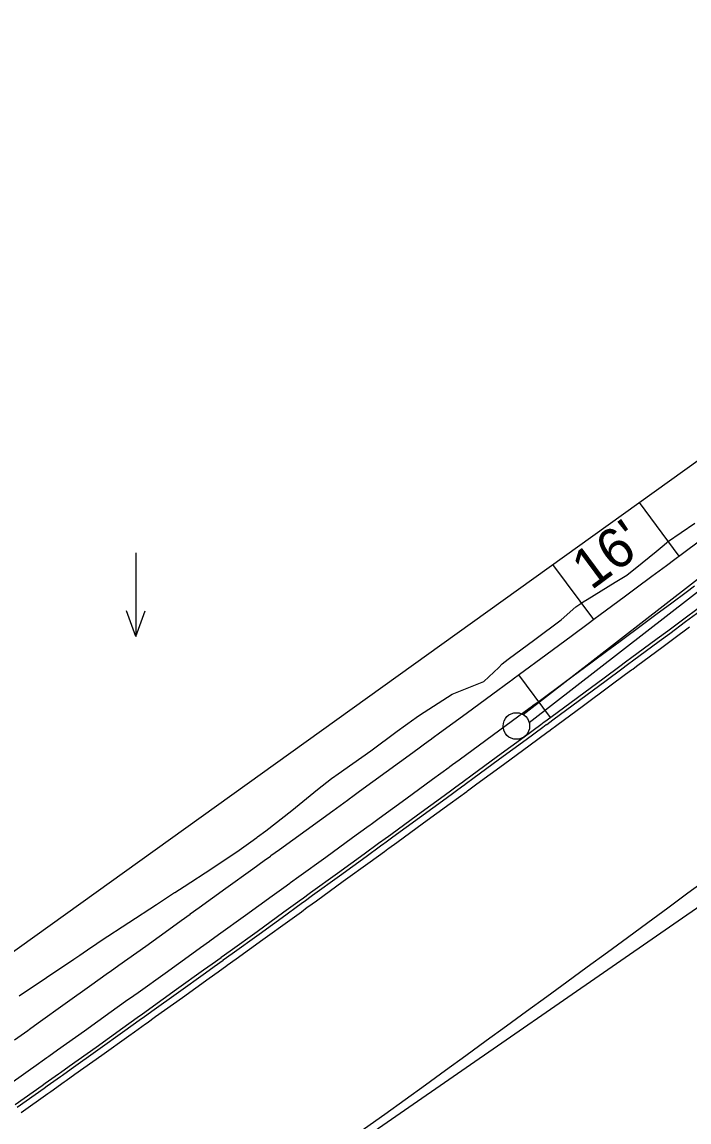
# Model space of a CAD drawing. Extents: x 1147550 to 1149124, y 2017436 to 2018779.
# Drawn here: x 1148333.9 to 1148434.3, y 2018092.6 to 2018257.9 of the extents above; entities that cross this region are included whole.
import ezdxf

# ---------------------------------------------------------------- set-up
doc = ezdxf.new("R2010")
doc.units = 0
for name, color, linetype in [('S_EDGE_CONCRETE', 7, 'Continuous'), ('S_HEADWALL', 7, 'Continuous'), ('S_MAILBOX', 7, 'Continuous'), ('S_SECONDARY_CTL', 7, 'Continuous'), ('S_TANK', 7, 'Continuous'), ('S_TELEPHONE_UTILITIES', 7, 'Continuous'), ('S_TELEPHONE_UTILITIES_ANNOT', 7, 'Continuous')]:
    doc.layers.add(name, color=color, linetype=linetype)

msp = doc.modelspace()

# ---------------------------------------------------------------- linework, layer by layer
at = {"layer": 'S_EDGE_CONCRETE'}
msp.add_line((1148293.22, 2018026.54), (1148491.47, 2018163.46), dxfattribs=at)
msp.add_arc((1145037.29, 2022741.09), 5729.58, 304.629463, 309.445337, dxfattribs=at)
at = {"layer": 'S_HEADWALL'}
for p, q in [((1148426.77, 2018185.69), (1148432.74, 2018177.64)), ((1148413.76, 2018176.37), (1148419.89, 2018168.11)), ((1148408.63, 2018159.79), (1148413.39, 2018153.37))]:
    msp.add_line(p, q, dxfattribs=at)
at = {"layer": 'S_MAILBOX'}
msp.add_lwpolyline([(1147550.1, 2017525.89), (1147894.72, 2017801.4), (1147903.55, 2017831.14), (1148035.64, 2017933.4), (1148261.5, 2018084.85), (1148285.74, 2018084.65), (1148479.1, 2018223.18), (1148835.76, 2018573.62)], dxfattribs=at)
at = {"layer": 'S_SECONDARY_CTL'}
msp.add_lwpolyline([(1148333.49, 2018111.55), (1148337.61, 2018114.33), (1148341.74, 2018117.07), (1148342.64, 2018117.69), (1148344.28, 2018118.81), (1148344.53, 2018118.98), (1148345.83, 2018119.87), (1148349.99, 2018122.59), (1148354.15, 2018125.3), (1148355.51, 2018126.18), (1148356.88, 2018127.08), (1148356.92, 2018127.1), (1148358.31, 2018128.01), (1148362.5, 2018130.68), (1148366.63, 2018133.43), (1148368.37, 2018134.7), (1148369.27, 2018135.36), (1148369.37, 2018135.43), (1148370.62, 2018136.38), (1148374.55, 2018139.42), (1148378.37, 2018142.59), (1148380.5, 2018144.22), (1148380.99, 2018144.57), (1148381.14, 2018144.67), (1148382.37, 2018145.53), (1148386.43, 2018148.38), (1148390.4, 2018151.36), (1148392.9, 2018153.14), (1148393.01, 2018153.22), (1148393.46, 2018153.52), (1148394.46, 2018154.21), (1148398.65, 2018156.88), (1148403.39, 2018158.81), (1148405.66, 2018160.92), (1148406.13, 2018161.39), (1148406.19, 2018161.44), (1148407.08, 2018162.16), (1148411.08, 2018165.1), (1148415.04, 2018168.08), (1148417.27, 2018170), (1148418.16, 2018170.63), (1148418.37, 2018170.77), (1148418.95, 2018171.15), (1148423.19, 2018173.75), (1148424.92, 2018174.76), (1148427.25, 2018176.62), (1148429.33, 2018178.36), (1148430.53, 2018179.36), (1148430.94, 2018179.7), (1148431.06, 2018179.8), (1148435.18, 2018182.58)], dxfattribs=at)
at = {"layer": 'S_TANK'}
for p, q in [((1148351.07, 2018178.15), (1148351.07, 2018165.58)), ((1148351.07, 2018165.58), (1148349.67, 2018169.43)), ((1148351.07, 2018165.58), (1148352.47, 2018169.43))]:
    msp.add_line(p, q, dxfattribs=at)
at = {"layer": 'S_TELEPHONE_UTILITIES'}
for points in [[(1148332.79, 2018104.94), (1148334.79, 2018106.36), (1148335.08, 2018106.57), (1148336.38, 2018107.5), (1148340.42, 2018110.38), (1148344.46, 2018113.26), (1148345.35, 2018113.89), (1148346.97, 2018115.06), (1148347.22, 2018115.23), (1148348.5, 2018116.15), (1148352.54, 2018119.04), (1148356.57, 2018121.94), (1148357.88, 2018122.88), (1148359.21, 2018123.84), (1148359.25, 2018123.86), (1148360.6, 2018124.83), (1148364.62, 2018127.74), (1148368.65, 2018130.64), (1148370.39, 2018131.9), (1148371.3, 2018132.56), (1148371.39, 2018132.63), (1148372.67, 2018133.55), (1148376.69, 2018136.46), (1148380.71, 2018139.38), (1148382.88, 2018140.95), (1148383.36, 2018141.31), (1148383.51, 2018141.41), (1148384.72, 2018142.3), (1148388.73, 2018145.22), (1148392.74, 2018148.15), (1148395.23, 2018149.96), (1148395.34, 2018150.04), (1148395.77, 2018150.36), (1148396.75, 2018151.08), (1148400.75, 2018154.01), (1148404.76, 2018156.95), (1148407.24, 2018158.77), (1148407.77, 2018159.16), (1148407.83, 2018159.21), (1148408.76, 2018159.89), (1148412.75, 2018162.83), (1148416.75, 2018165.78), (1148419.1, 2018167.52), (1148419.98, 2018168.17), (1148420.18, 2018168.32), (1148420.74, 2018168.73), (1148424.73, 2018171.68), (1148426.32, 2018172.87), (1148428.71, 2018174.64), (1148430.89, 2018176.26), (1148432.14, 2018177.19), (1148432.57, 2018177.51), (1148432.7, 2018177.6), (1148436.68, 2018180.57)], [(1148331.18, 2018097.67), (1148335.23, 2018100.54), (1148335.69, 2018100.87), (1148337.69, 2018102.29), (1148337.98, 2018102.5), (1148339.28, 2018103.42), (1148343.33, 2018106.31), (1148347.37, 2018109.19), (1148348.25, 2018109.83), (1148349.88, 2018110.99), (1148350.13, 2018111.16), (1148351.41, 2018112.08), (1148355.45, 2018114.98), (1148359.49, 2018117.88), (1148360.8, 2018118.82), (1148362.13, 2018119.78), (1148362.17, 2018119.81), (1148363.52, 2018120.78), (1148367.55, 2018123.68), (1148371.58, 2018126.59), (1148373.32, 2018127.85), (1148374.23, 2018128.5), (1148374.32, 2018128.57), (1148375.6, 2018129.5), (1148379.63, 2018132.42), (1148383.65, 2018135.33), (1148385.82, 2018136.91), (1148386.31, 2018137.27), (1148386.45, 2018137.37), (1148387.66, 2018138.26), (1148391.68, 2018141.18), (1148395.69, 2018144.11), (1148398.18, 2018145.93), (1148398.29, 2018146.01), (1148398.72, 2018146.33), (1148399.7, 2018147.04), (1148403.71, 2018149.98), (1148407.72, 2018152.92), (1148410.2, 2018154.75), (1148410.73, 2018155.14), (1148410.8, 2018155.18), (1148411.72, 2018155.86), (1148415.72, 2018158.81), (1148419.72, 2018161.76), (1148422.08, 2018163.5), (1148422.96, 2018164.15), (1148423.16, 2018164.3), (1148423.71, 2018164.71), (1148427.7, 2018167.67), (1148429.3, 2018168.85), (1148431.69, 2018170.63), (1148433.87, 2018172.25), (1148435.13, 2018173.18)], [(1148332.92, 2018095.22), (1148336.97, 2018098.1), (1148337.42, 2018098.42), (1148339.43, 2018099.84), (1148339.72, 2018100.05), (1148341.02, 2018100.98), (1148345.07, 2018103.86), (1148349.11, 2018106.75), (1148350, 2018107.39), (1148351.63, 2018108.55), (1148351.87, 2018108.72), (1148353.16, 2018109.64), (1148357.2, 2018112.54), (1148361.24, 2018115.44), (1148362.55, 2018116.38), (1148363.88, 2018117.34), (1148363.92, 2018117.37), (1148365.27, 2018118.34), (1148369.3, 2018121.25), (1148373.33, 2018124.16), (1148375.08, 2018125.42), (1148375.98, 2018126.07), (1148376.08, 2018126.14), (1148377.36, 2018127.07), (1148381.39, 2018129.99), (1148385.41, 2018132.91), (1148387.58, 2018134.48), (1148388.07, 2018134.84), (1148388.21, 2018134.95), (1148389.43, 2018135.83), (1148393.45, 2018138.76), (1148397.46, 2018141.69), (1148399.95, 2018143.51), (1148400.06, 2018143.59), (1148400.49, 2018143.9), (1148401.48, 2018144.62), (1148405.49, 2018147.56), (1148409.49, 2018150.5), (1148411.98, 2018152.33), (1148412.51, 2018152.72), (1148412.57, 2018152.77), (1148413.5, 2018153.45), (1148417.5, 2018156.39), (1148421.5, 2018159.34), (1148423.86, 2018161.09), (1148424.74, 2018161.74), (1148424.94, 2018161.89), (1148425.5, 2018162.3), (1148429.49, 2018165.26), (1148431.09, 2018166.44), (1148433.48, 2018168.22), (1148435.66, 2018169.84)], [(1148333.21, 2018094.81), (1148337.26, 2018097.69), (1148337.71, 2018098.01), (1148339.72, 2018099.44), (1148340.01, 2018099.65), (1148341.31, 2018100.57), (1148345.36, 2018103.46), (1148349.41, 2018106.35), (1148350.29, 2018106.98), (1148351.92, 2018108.14), (1148352.16, 2018108.32), (1148353.45, 2018109.24), (1148357.49, 2018112.13), (1148361.53, 2018115.03), (1148362.84, 2018115.98), (1148364.18, 2018116.94), (1148364.21, 2018116.96), (1148365.56, 2018117.94), (1148369.6, 2018120.84), (1148373.63, 2018123.75), (1148375.37, 2018125.01), (1148376.28, 2018125.67), (1148376.38, 2018125.74), (1148377.66, 2018126.67), (1148381.68, 2018129.58), (1148385.7, 2018132.5), (1148387.87, 2018134.08), (1148388.36, 2018134.44), (1148388.51, 2018134.54), (1148389.72, 2018135.43), (1148393.74, 2018138.35), (1148397.76, 2018141.28), (1148400.24, 2018143.1), (1148400.35, 2018143.18), (1148400.79, 2018143.5), (1148401.77, 2018144.22), (1148405.78, 2018147.16), (1148409.79, 2018150.1), (1148412.28, 2018151.93), (1148412.81, 2018152.32), (1148412.87, 2018152.36), (1148413.79, 2018153.04), (1148417.8, 2018155.99), (1148421.8, 2018158.94), (1148424.16, 2018160.69), (1148425.04, 2018161.34), (1148425.24, 2018161.49), (1148425.79, 2018161.9), (1148429.79, 2018164.86), (1148431.39, 2018166.04), (1148433.78, 2018167.82), (1148435.96, 2018169.44)], [(1148333.79, 2018094), (1148337.84, 2018096.88), (1148338.29, 2018097.2), (1148340.3, 2018098.62), (1148340.59, 2018098.83), (1148341.89, 2018099.76), (1148345.94, 2018102.64), (1148349.99, 2018105.53), (1148350.87, 2018106.17), (1148352.5, 2018107.33), (1148352.74, 2018107.5), (1148354.03, 2018108.43), (1148358.07, 2018111.32), (1148362.11, 2018114.22), (1148363.43, 2018115.17), (1148364.76, 2018116.13), (1148364.8, 2018116.15), (1148366.15, 2018117.12), (1148370.18, 2018120.03), (1148374.21, 2018122.94), (1148375.96, 2018124.2), (1148376.86, 2018124.86), (1148376.96, 2018124.93), (1148378.24, 2018125.86), (1148382.27, 2018128.77), (1148386.29, 2018131.69), (1148388.46, 2018133.27), (1148388.95, 2018133.63), (1148389.1, 2018133.73), (1148390.31, 2018134.62), (1148394.33, 2018137.55), (1148398.35, 2018140.48), (1148400.84, 2018142.29), (1148400.94, 2018142.37), (1148401.38, 2018142.69), (1148402.36, 2018143.41), (1148406.37, 2018146.35), (1148410.38, 2018149.29), (1148412.87, 2018151.12), (1148413.4, 2018151.51), (1148413.46, 2018151.56), (1148414.39, 2018152.24), (1148418.39, 2018155.19), (1148422.39, 2018158.14), (1148424.75, 2018159.88), (1148425.63, 2018160.53), (1148425.83, 2018160.68), (1148426.39, 2018161.09), (1148430.38, 2018164.05), (1148431.98, 2018165.24), (1148434.38, 2018167.02)]]:
    msp.add_lwpolyline(points, dxfattribs=at)
at = {"layer": 'S_TELEPHONE_UTILITIES_ANNOT'}
for p, q in [((1148409.31, 2018153.84), (1148641.93, 2018334.28)), ((1148409.31, 2018153.84), (1148641.93, 2018334.28)), ((1148410.23, 2018152.66), (1148642.85, 2018333.1)), ((1148410.23, 2018152.66), (1148642.85, 2018333.1))]:
    msp.add_line(p, q, dxfattribs=at)
msp.add_circle((1148408.31, 2018152.11), 2, dxfattribs=at)

# ---------------------------------------------------------------- texts
at = {"layer": 'S_HEADWALL'}
msp.add_text("16'", height=6, rotation=36.5706, dxfattribs=at).set_placement((1148419.57, 2018172.43))

doc.saveas('drawing.dxf')
